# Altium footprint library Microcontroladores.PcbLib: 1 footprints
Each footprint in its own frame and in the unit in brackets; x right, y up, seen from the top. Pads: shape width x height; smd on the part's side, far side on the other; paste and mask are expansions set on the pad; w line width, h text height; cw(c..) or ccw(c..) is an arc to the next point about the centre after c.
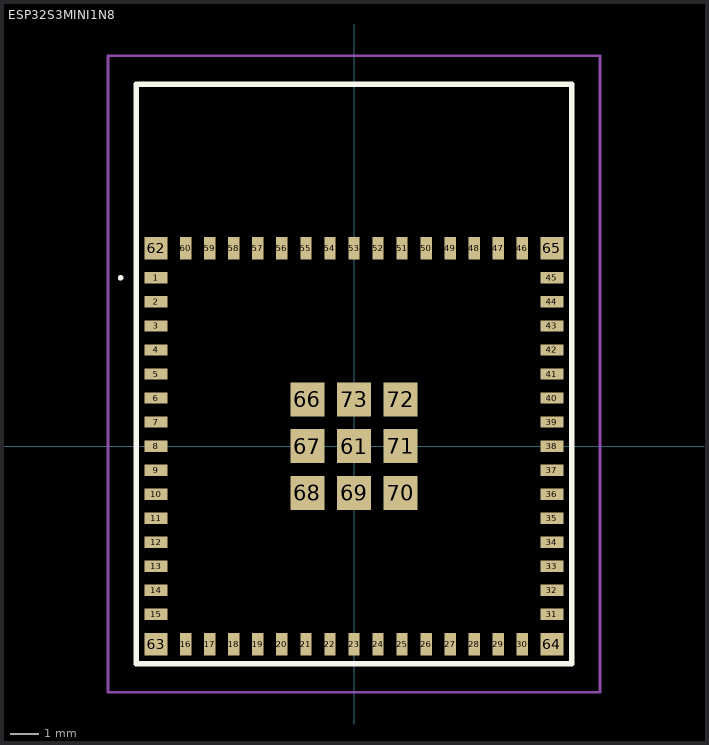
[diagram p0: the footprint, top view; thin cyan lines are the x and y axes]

## ESP32S3MINI1N8 [mm]
pads (73):
  rect 0.8x0.4 smd: 1(-7,5.95) 2(-7,5.1) 3(-7,4.25) 4(-7,3.4) 5(-7,2.55) 6(-7,1.7) 7(-7,0.85) 8(-7,0) 9(-7,-0.85) 10(-7,-1.7) 11(-7,-2.55) 12(-7,-3.4) 13(-7,-4.25) 14(-7,-5.1) 15(-7,-5.95) 31(7,-5.95) 32(7,-5.1) 33(7,-4.25) 34(7,-3.4) 35(7,-2.55) 36(7,-1.7) 37(7,-0.85) 38(7,0) 39(7,0.85) 40(7,1.7) 41(7,2.55) 42(7,3.4) 43(7,4.25) 44(7,5.1) 45(7,5.95)
  rect 0.4x0.8 smd: 16(-5.95,-7) 17(-5.1,-7) 18(-4.25,-7) 19(-3.4,-7) 20(-2.55,-7) 21(-1.7,-7) 22(-0.85,-7) 23(0,-7) 24(0.85,-7) 25(1.7,-7) 26(2.55,-7) 27(3.4,-7) 28(4.25,-7) 29(5.1,-7) 30(5.95,-7) 46(5.95,7) 47(5.1,7) 48(4.25,7) 49(3.4,7) 50(2.55,7) 51(1.7,7) 52(0.85,7) 53(0,7) 54(-0.85,7) 55(-1.7,7) 56(-2.55,7) 57(-3.4,7) 58(-4.25,7) 59(-5.1,7) 60(-5.95,7)
  rect 1.2x1.2 smd: 61(0,0) 66(-1.65,1.65) 67(-1.65,0) 68(-1.65,-1.65) 69(0,-1.65) 70(1.65,-1.65) 71(1.65,0) 72(1.65,1.65) 73(0,1.65)
  rect 0.8x0.8 smd: 62(-7,7) 63(-7,-7) 64(7,-7) 65(7,7)
Top Overlay:
  lines w0.1: -8.3,5.95 cw(c-8.25,5.95) -8.2,5.95 cw(c-8.25,5.95) -8.3,5.95
  lines w0.2: -7.7,-7.7 7.7,-7.7 7.7,12.8 -7.7,12.8 -7.7,-7.7
Mechanical 13:
  lines w0.1: -7.7,-7.7 7.7,-7.7 7.7,12.8 -7.7,12.8 -7.7,-7.7
Mechanical 15:
  lines w0.1: -8.7,-8.7 8.7,-8.7 8.7,13.8 -8.7,13.8 -8.7,-8.7
3D body "ESP32-S3-MINI-1-N8.stp": height 2.55, standoff 0, extent -7.7,-7.695 7.7,12.805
